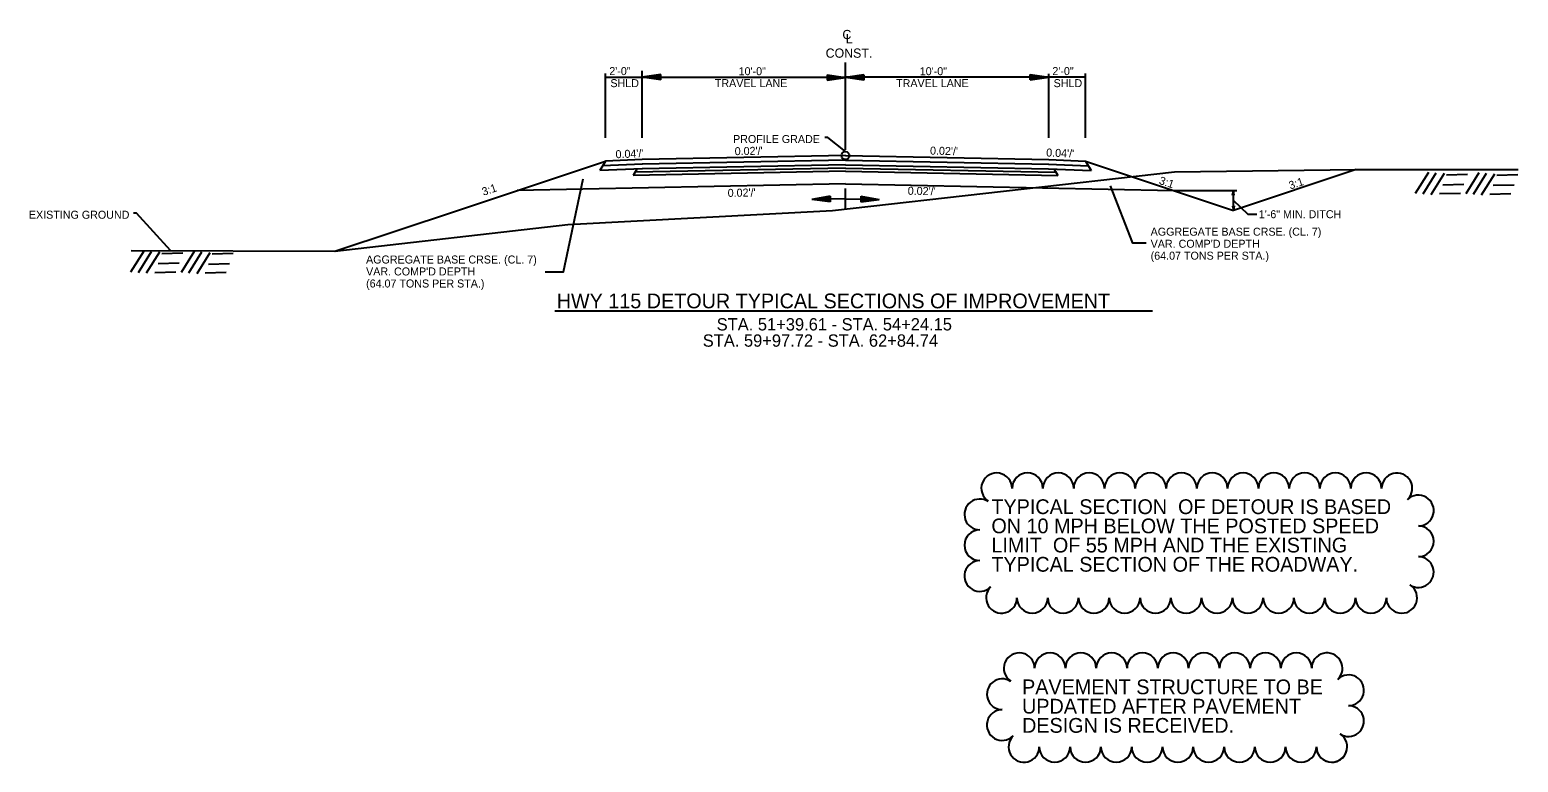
# Model space of a CAD drawing. Extents: x 1373719 to 1374161, y 379835 to 380167.
# Drawn here: x 1373742.6 to 1373863.5, y 379927.3 to 379986.8 of the extents above; entities that cross this region are included whole.
import ezdxf

# ---------------------------------------------------------------- set-up
doc = ezdxf.new("R2010")
doc.units = 0
for name, color, linetype in [('_30% NOTES', 7, 'Continuous'), ('Agg Base Course Text', 7, 'Continuous'), ('CL Construction', 7, 'Continuous'), ('GREEN_TXT', 7, 'Continuous'), ('Ground Hatch', 7, 'Continuous'), ('Pavement Layers', 7, 'Continuous'), ('SEAL-INFO', 7, 'Continuous'), ('T_Drafting', 7, 'Continuous')]:
    doc.layers.add(name, color=color, linetype=linetype)

msp = doc.modelspace()

# ---------------------------------------------------------------- linework, layer by layer
for p, q in [((1373808.87, 379976.62), (1373792.37, 379976.29)), ((1373808.87, 379976.62), (1373825.37, 379976.29)), ((1373777.37, 379972.17), (1373789.37, 379976.17)), ((1373792.37, 379976.29), (1373789.37, 379976.17)), ((1373825.37, 379976.29), (1373828.37, 379976.17)), ((1373828.37, 379976.17), (1373840.37, 379972.17)), ((1373850.33, 379975.49), (1373840.37, 379972.17)), ((1373808.87, 379974.32), (1373782.22, 379973.79)), ((1373808.87, 379974.32), (1373835.52, 379973.79)), ((1373767.41, 379968.85), (1373777.37, 379972.17))]:
    msp.add_line(p, q)
at = {"layer": '_30% NOTES'}
for centre, start, end in [((1373821.15, 379949.58), 0, 236.9636), ((1373823.65, 379949.58), 0, 180), ((1373826.15, 379949.58), 0, 180), ((1373828.65, 379949.58), 0, 180), ((1373831.15, 379949.58), 0, 180), ((1373833.65, 379949.58), 0, 180), ((1373836.15, 379949.58), 0, 180), ((1373838.65, 379949.58), 0, 180), ((1373841.15, 379949.58), 0, 180), ((1373843.65, 379949.58), 0, 180), ((1373846.15, 379949.58), 0, 180), ((1373848.65, 379949.58), 0, 180), ((1373851.15, 379949.58), 0, 180), ((1373853.65, 379949.58), 314.1183, 180), ((1373819.78, 379947.46), 56.9636, 270), ((1373855.39, 379947.78), 270, 134.1183), ((1373855.39, 379945.28), 270, 90), ((1373819.78, 379944.96), 90, 270), ((1373855.39, 379942.78), 237.0496, 90), ((1373819.78, 379942.46), 90, 314.8317), ((1373821.54, 379940.69), 134.8317, 0), ((1373854.04, 379940.69), 180, 57.0496), ((1373824.04, 379940.69), 180, 0), ((1373826.54, 379940.69), 180, 0), ((1373829.04, 379940.69), 180, 0), ((1373831.54, 379940.69), 180, 0), ((1373834.04, 379940.69), 180, 0), ((1373836.54, 379940.69), 180, 0), ((1373839.04, 379940.69), 180, 0), ((1373841.54, 379940.69), 180, 0), ((1373844.04, 379940.69), 180, 0), ((1373846.54, 379940.69), 180, 0), ((1373849.04, 379940.69), 180, 0), ((1373851.54, 379940.69), 180, 0), ((1373822.98, 379934.96), 0, 236.9636), ((1373825.48, 379934.96), 0, 180), ((1373827.98, 379934.96), 0, 180), ((1373830.48, 379934.96), 0, 180), ((1373832.98, 379934.96), 0, 180), ((1373835.48, 379934.96), 0, 180), ((1373837.98, 379934.96), 0, 180), ((1373840.48, 379934.96), 0, 180), ((1373842.98, 379934.96), 0, 180), ((1373845.48, 379934.96), 0, 180), ((1373847.98, 379934.96), 314.1183, 180), ((1373849.72, 379933.17), 270, 134.1183), ((1373821.6, 379932.85), 56.9636, 270), ((1373849.72, 379930.67), 237.0496, 90), ((1373821.6, 379930.35), 90, 314.8317), ((1373823.36, 379928.58), 134.8317, 0), ((1373848.36, 379928.58), 180, 57.0496), ((1373825.86, 379928.58), 180, 0), ((1373828.36, 379928.58), 180, 0), ((1373830.86, 379928.58), 180, 0), ((1373833.36, 379928.58), 180, 0), ((1373835.86, 379928.58), 180, 0), ((1373838.36, 379928.58), 180, 0), ((1373840.86, 379928.58), 180, 0), ((1373843.36, 379928.58), 180, 0), ((1373845.86, 379928.58), 180, 0), ((1373848.36, 379928.58), 180, 0)]:
    msp.add_arc(centre, 1.25, start, end, dxfattribs=at)
at = {"layer": 'Agg Base Course Text'}
for points in [[(1373784.48, 379967.17), (1373785.97, 379967.17), (1373787.56, 379974.72)], [(1373833.29, 379969.5), (1373832.21, 379969.5), (1373830.38, 379974.16)]]:
    msp.add_lwpolyline(points, dxfattribs=at)
at = {"layer": 'CL Construction'}
msp.add_line((1373808.87, 379977.1), (1373808.87, 379984.19), dxfattribs=at)
at = {"layer": 'GREEN_TXT'}
for p, q in [((1373789.37, 379982.73), (1373789.37, 379983.3)), ((1373789.37, 379982.99), (1373792.37, 379982.99)), ((1373789.37, 379978.07), (1373789.37, 379982.73)), ((1373792.37, 379982.73), (1373792.37, 379983.5)), ((1373793.87, 379983.22), (1373792.37, 379982.99)), ((1373793.87, 379982.77), (1373792.37, 379982.99)), ((1373792.37, 379982.99), (1373808.87, 379982.99)), ((1373792.37, 379978.07), (1373792.37, 379982.73)), ((1373793.87, 379983.18), (1373792.62, 379982.99)), ((1373793.87, 379982.8), (1373792.62, 379982.99)), ((1373793.87, 379983.14), (1373792.88, 379982.99)), ((1373793.87, 379982.84), (1373792.88, 379982.99)), ((1373793.87, 379983.1), (1373793.13, 379982.99)), ((1373793.87, 379982.88), (1373793.13, 379982.99)), ((1373793.87, 379983.07), (1373793.38, 379982.99)), ((1373793.87, 379982.92), (1373793.38, 379982.99)), ((1373793.87, 379983.03), (1373793.63, 379982.99)), ((1373793.87, 379982.96), (1373793.63, 379982.99)), ((1373793.87, 379982.77), (1373793.87, 379983.22)), ((1373807.37, 379983.19), (1373808.87, 379982.96)), ((1373807.37, 379983.19), (1373807.37, 379982.74)), ((1373807.37, 379983.19), (1373808.87, 379982.96)), ((1373807.37, 379983.19), (1373807.37, 379982.74)), ((1373807.37, 379983.15), (1373808.62, 379982.96)), ((1373807.37, 379983.15), (1373808.62, 379982.96)), ((1373807.37, 379983.11), (1373808.36, 379982.96)), ((1373807.37, 379983.11), (1373808.36, 379982.96)), ((1373807.37, 379983.07), (1373808.11, 379982.96)), ((1373807.37, 379983.07), (1373808.11, 379982.96)), ((1373807.37, 379983.03), (1373807.86, 379982.96)), ((1373807.37, 379983.03), (1373807.86, 379982.96)), ((1373807.37, 379983), (1373807.61, 379982.96)), ((1373807.37, 379983), (1373807.61, 379982.96)), ((1373807.37, 379982.74), (1373808.87, 379982.96)), ((1373807.37, 379982.89), (1373807.86, 379982.96)), ((1373807.37, 379982.81), (1373808.36, 379982.96)), ((1373807.37, 379982.77), (1373808.62, 379982.96)), ((1373807.37, 379982.85), (1373808.11, 379982.96)), ((1373807.37, 379982.93), (1373807.61, 379982.96)), ((1373807.37, 379982.74), (1373808.87, 379982.96)), ((1373807.37, 379982.89), (1373807.86, 379982.96)), ((1373807.37, 379982.81), (1373808.36, 379982.96)), ((1373807.37, 379982.77), (1373808.62, 379982.96)), ((1373807.37, 379982.85), (1373808.11, 379982.96)), ((1373807.37, 379982.93), (1373807.61, 379982.96)), ((1373810.37, 379983.19), (1373808.87, 379982.96)), ((1373810.37, 379983.19), (1373808.87, 379982.96)), ((1373825.37, 379982.99), (1373808.87, 379982.99)), ((1373810.37, 379982.74), (1373808.87, 379982.96)), ((1373810.37, 379982.74), (1373808.87, 379982.96)), ((1373810.37, 379983.15), (1373809.12, 379982.96)), ((1373810.37, 379983.15), (1373809.12, 379982.96)), ((1373810.37, 379982.77), (1373809.12, 379982.96)), ((1373810.37, 379982.77), (1373809.12, 379982.96)), ((1373810.37, 379983.11), (1373809.38, 379982.96)), ((1373810.37, 379983.11), (1373809.38, 379982.96)), ((1373810.37, 379982.81), (1373809.38, 379982.96)), ((1373810.37, 379982.81), (1373809.38, 379982.96)), ((1373810.37, 379983.07), (1373809.63, 379982.96)), ((1373810.37, 379983.07), (1373809.63, 379982.96)), ((1373810.37, 379982.85), (1373809.63, 379982.96)), ((1373810.37, 379982.85), (1373809.63, 379982.96)), ((1373810.37, 379983.03), (1373809.88, 379982.96)), ((1373810.37, 379983.03), (1373809.88, 379982.96)), ((1373810.37, 379982.89), (1373809.88, 379982.96)), ((1373810.37, 379982.89), (1373809.88, 379982.96)), ((1373810.37, 379983), (1373810.13, 379982.96)), ((1373810.37, 379983), (1373810.13, 379982.96)), ((1373810.37, 379982.93), (1373810.13, 379982.96)), ((1373810.37, 379982.93), (1373810.13, 379982.96)), ((1373810.37, 379983.19), (1373810.37, 379982.74)), ((1373810.37, 379983.19), (1373810.37, 379982.74)), ((1373823.87, 379983.22), (1373825.37, 379982.99)), ((1373823.87, 379982.77), (1373823.87, 379983.22)), ((1373823.87, 379983.18), (1373825.12, 379982.99)), ((1373823.87, 379983.14), (1373824.86, 379982.99)), ((1373823.87, 379983.1), (1373824.61, 379982.99)), ((1373823.87, 379983.07), (1373824.36, 379982.99)), ((1373823.87, 379983.03), (1373824.11, 379982.99)), ((1373823.87, 379982.77), (1373825.37, 379982.99)), ((1373823.87, 379982.92), (1373824.36, 379982.99)), ((1373823.87, 379982.84), (1373824.86, 379982.99)), ((1373823.87, 379982.8), (1373825.12, 379982.99)), ((1373823.87, 379982.88), (1373824.61, 379982.99)), ((1373823.87, 379982.96), (1373824.11, 379982.99)), ((1373825.37, 379982.73), (1373825.37, 379983.27)), ((1373828.37, 379982.99), (1373825.37, 379982.99)), ((1373825.37, 379978.07), (1373825.37, 379982.73)), ((1373828.37, 379982.73), (1373828.37, 379983.3)), ((1373828.37, 379978.07), (1373828.37, 379982.73)), ((1373807.62, 379973.31), (1373806.13, 379973.06)), ((1373808.87, 379973.11), (1373806.13, 379973.06)), ((1373807.63, 379972.86), (1373806.13, 379973.06)), ((1373807.63, 379973.28), (1373806.38, 379973.06)), ((1373807.63, 379972.9), (1373806.38, 379973.06)), ((1373807.63, 379973.24), (1373806.64, 379973.07)), ((1373807.63, 379972.94), (1373806.64, 379973.07)), ((1373807.63, 379973.2), (1373806.89, 379973.07)), ((1373807.63, 379972.98), (1373806.89, 379973.07)), ((1373807.63, 379973.16), (1373807.14, 379973.08)), ((1373807.63, 379973.02), (1373807.14, 379973.08)), ((1373807.63, 379973.12), (1373807.39, 379973.08)), ((1373807.63, 379973.05), (1373807.39, 379973.08)), ((1373807.62, 379973.31), (1373807.63, 379972.86)), ((1373808.87, 379972.26), (1373808.87, 379973.94)), ((1373808.87, 379973.11), (1373811.61, 379973.06)), ((1373810.12, 379973.31), (1373810.11, 379972.86)), ((1373810.11, 379973.28), (1373811.36, 379973.06)), ((1373810.11, 379973.24), (1373811.1, 379973.07)), ((1373810.11, 379973.2), (1373810.85, 379973.07)), ((1373810.11, 379973.16), (1373810.6, 379973.08)), ((1373810.11, 379973.12), (1373810.35, 379973.08)), ((1373810.11, 379973.02), (1373810.6, 379973.08)), ((1373810.11, 379973.05), (1373810.35, 379973.08)), ((1373810.11, 379972.94), (1373811.1, 379973.07)), ((1373810.11, 379972.98), (1373810.85, 379973.07)), ((1373810.11, 379972.86), (1373811.61, 379973.06)), ((1373810.11, 379972.9), (1373811.36, 379973.06)), ((1373810.12, 379973.31), (1373811.61, 379973.06)), ((1373835.52, 379973.79), (1373840.65, 379973.79)), ((1373840.31, 379973.41), (1373840.37, 379973.79)), ((1373840.43, 379973.41), (1373840.31, 379973.41)), ((1373840.32, 379973.41), (1373840.37, 379973.72)), ((1373840.33, 379973.41), (1373840.37, 379973.66)), ((1373840.34, 379973.41), (1373840.37, 379973.6)), ((1373840.35, 379973.41), (1373840.37, 379973.53)), ((1373840.36, 379973.41), (1373840.37, 379973.47)), ((1373840.37, 379972.17), (1373840.37, 379973.79)), ((1373840.43, 379973.41), (1373840.37, 379973.79)), ((1373840.42, 379973.41), (1373840.37, 379973.72)), ((1373840.41, 379973.41), (1373840.37, 379973.66)), ((1373840.4, 379973.41), (1373840.37, 379973.6)), ((1373840.39, 379973.41), (1373840.37, 379973.53)), ((1373840.38, 379973.41), (1373840.37, 379973.47)), ((1373840.31, 379972.54), (1373840.37, 379972.17)), ((1373840.31, 379972.54), (1373840.43, 379972.54)), ((1373840.32, 379972.54), (1373840.37, 379972.23)), ((1373840.33, 379972.54), (1373840.37, 379972.3)), ((1373840.34, 379972.54), (1373840.37, 379972.36)), ((1373840.35, 379972.54), (1373840.37, 379972.42)), ((1373840.36, 379972.54), (1373840.37, 379972.48)), ((1373840.43, 379972.54), (1373840.37, 379972.17)), ((1373840.39, 379972.54), (1373840.37, 379972.42)), ((1373840.41, 379972.54), (1373840.37, 379972.3)), ((1373840.42, 379972.54), (1373840.37, 379972.23)), ((1373840.4, 379972.54), (1373840.37, 379972.36)), ((1373840.38, 379972.54), (1373840.37, 379972.48)), ((1373785.26, 379964.01), (1373833.8, 379964.01))]:
    msp.add_line(p, q, dxfattribs=at)
for points in [[(1373808.87, 379976.94), (1373807.44, 379978.09), (1373807.2, 379978.09)], [(1373754.07, 379968.91), (1373751.31, 379971.94), (1373751.06, 379971.94)]]:
    msp.add_lwpolyline(points, dxfattribs=at)
at = {"layer": 'Ground Hatch'}
for p, q in [((1373855.17, 379973.57), (1373856.24, 379975.28)), ((1373855.77, 379973.52), (1373856.84, 379975.23)), ((1373856.44, 379973.47), (1373857.51, 379975.18)), ((1373857.37, 379974.25), (1373859.07, 379974.29)), ((1373857.68, 379975.06), (1373859.37, 379975.11)), ((1373859.26, 379973.53), (1373860.33, 379975.24)), ((1373859.86, 379973.48), (1373860.93, 379975.19)), ((1373860.53, 379973.44), (1373861.6, 379975.14)), ((1373861.46, 379974.21), (1373863.16, 379974.25)), ((1373861.77, 379975.03), (1373863.47, 379975.07)), ((1373857.11, 379973.53), (1373858.8, 379973.57)), ((1373861.2, 379973.49), (1373862.89, 379973.53)), ((1373750.85, 379967.17), (1373751.92, 379968.88)), ((1373751.45, 379967.13), (1373752.52, 379968.83)), ((1373752.12, 379967.08), (1373753.19, 379968.79)), ((1373753.36, 379968.67), (1373755.06, 379968.71)), ((1373754.95, 379967.14), (1373756.01, 379968.84)), ((1373755.55, 379967.09), (1373756.61, 379968.8)), ((1373756.22, 379967.04), (1373757.28, 379968.75)), ((1373757.45, 379968.63), (1373759.15, 379968.68)), ((1373752.79, 379967.13), (1373754.49, 379967.18)), ((1373753.06, 379967.85), (1373754.75, 379967.9)), ((1373756.88, 379967.09), (1373758.58, 379967.14)), ((1373757.15, 379967.81), (1373758.84, 379967.86))]:
    msp.add_line(p, q, dxfattribs=at)
at = {"layer": 'Pavement Layers'}
for p, q in [((1373789.37, 379976.17), (1373788.92, 379975.4)), ((1373792.38, 379975.53), (1373788.92, 379975.4)), ((1373792.38, 379975.92), (1373789.15, 379975.79)), ((1373791.92, 379975.52), (1373791.63, 379975.01)), ((1373808.87, 379975.35), (1373791.63, 379975.01)), ((1373808.87, 379975.61), (1373791.78, 379975.27)), ((1373808.87, 379976.25), (1373792.37, 379975.92)), ((1373808.87, 379975.86), (1373792.37, 379975.53)), ((1373808.87, 379976.25), (1373825.37, 379975.92)), ((1373808.87, 379975.86), (1373825.36, 379975.53)), ((1373808.87, 379975.61), (1373825.96, 379975.27)), ((1373808.87, 379975.35), (1373826.11, 379975.01)), ((1373825.36, 379975.92), (1373828.59, 379975.79)), ((1373825.36, 379975.53), (1373828.82, 379975.4)), ((1373825.82, 379975.52), (1373826.11, 379975.01)), ((1373828.37, 379976.17), (1373828.82, 379975.4))]:
    msp.add_line(p, q, dxfattribs=at)
at = {"layer": 'SEAL-INFO'}
msp.add_lwpolyline([(1373842.27, 379971.82), (1373841.57, 379971.82), (1373840.37, 379972.98)], dxfattribs=at)
msp.add_circle((1373808.87, 379976.62), 0.325, dxfattribs=at)
at = {"layer": 'T_Drafting'}
msp.add_lwpolyline([(1373750.86, 379968.92), (1373767.41, 379968.85), (1373786.33, 379971.02), (1373807.82, 379972.17), (1373835.59, 379975.29), (1373850.33, 379975.49), (1373863.5, 379975.49)], dxfattribs=at)

# ---------------------------------------------------------------- texts
at = {"layer": '_30% NOTES'}
for s, p in [('TYPICAL SECTION  OF DETOUR IS BASED', (1373820.72, 379947.49)), ('ON 10 MPH BELOW THE POSTED SPEED', (1373820.72, 379945.93)), ('LIMIT  OF 55 MPH AND THE EXISTING', (1373820.72, 379944.37)), ('TYPICAL SECTION OF THE ROADWAY.', (1373820.72, 379942.81)), ('PAVEMENT STRUCTURE TO BE', (1373823.21, 379932.85)), ('UPDATED AFTER PAVEMENT', (1373823.21, 379931.28)), ('DESIGN IS RECEIVED.', (1373823.21, 379929.72))]:
    msp.add_text(s, height=1.2, dxfattribs=at).set_placement(p)
at = {"layer": 'Agg Base Course Text'}
for s, p in [('AGGREGATE BASE CRSE. (CL. 7)', (1373833.65, 379970.11)), ("VAR. COMP'D DEPTH", (1373833.65, 379969.13)), ('AGGREGATE BASE CRSE. (CL. 7)', (1373769.94, 379967.85)), ('(64.07 TONS PER STA.)', (1373833.65, 379968.16)), ("VAR. COMP'D DEPTH", (1373769.94, 379966.88)), ('(64.07 TONS PER STA.)', (1373769.94, 379965.9))]:
    msp.add_text(s, height=0.65, dxfattribs=at).set_placement(p)
at = {"layer": 'GREEN_TXT'}
for s, height, p in [('2\'-0"', 0.65, (1373789.69, 379983.16)), ('10\'-0"', 0.65, (1373800.19, 379983.15)), ('10\'-0"', 0.65, (1373814.9, 379983.15)), ('2\'-0"', 0.65, (1373825.67, 379983.16)), ('SHLD', 0.65, (1373789.78, 379982.18)), ('TRAVEL LANE', 0.65, (1373798.26, 379982.18)), ('TRAVEL LANE', 0.65, (1373812.98, 379982.18)), ('SHLD', 0.65, (1373825.77, 379982.18)), ('1\'-6" MIN. DITCH', 0.65, (1373842.43, 379971.53)), ('HWY 115 DETOUR TYPICAL SECTIONS OF IMPROVEMENT', 1.2, (1373785.42, 379964.21)), ('STA. 51+39.61 - STA. 54+24.15', 1, (1373798.41, 379962.41)), ('STA. 59+97.72 - STA. 62+84.74', 1, (1373797.28, 379961.09))]:
    msp.add_text(s, height=height, dxfattribs=at).set_placement(p)
for s, rotation, p in [('PROFILE GRADE', 359.98, (1373799.74, 379977.64)), ("0.04'/'", 2.2906, (1373790.21, 379976.4)), ("0.02'/'", 1.1458, (1373799.88, 379976.65)), ("0.02'/'", 358.8542, (1373815.73, 379976.7)), ("0.04'/'", 357.7094, (1373825.16, 379976.55)), ('3:1', 18.4349, (1373779.47, 379973.35)), ("0.02'/'", 358.854, (1373813.92, 379973.44)), ('3:1', 341.5651, (1373834.28, 379974.33)), ('3:1', 18.4349, (1373844.99, 379973.86)), ("0.02'/'", 1.146, (1373799.31, 379973.26)), ('EXISTING GROUND', 359.98, (1373742.56, 379971.49))]:
    msp.add_text(s, height=0.65, rotation=rotation, dxfattribs=at).set_placement(p)
at = {"layer": 'SEAL-INFO'}
for s, p in [('C', (1373808.62, 379986.08)), ('L', (1373808.89, 379985.75)), ('CONST.', (1373807.26, 379984.57))]:
    msp.add_text(s, height=0.75, dxfattribs=at).set_placement(p)

doc.saveas('drawing.dxf')
